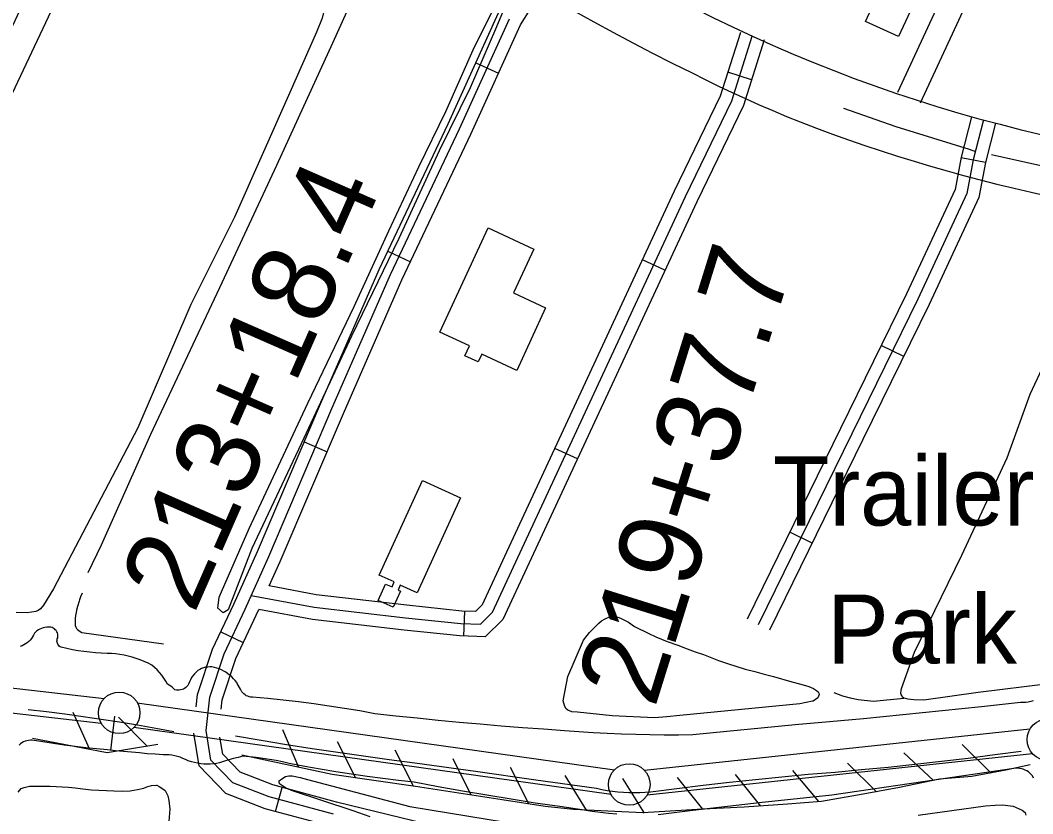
# Model space of a CAD drawing. Extents: x 3704301 to 3742427, y 506229 to 532009.
# Drawn here: x 3716465 to 3717682, y 522042 to 522996 of the extents above; entities that cross this region are included whole.
import ezdxf

# ---------------------------------------------------------------- set-up
doc = ezdxf.new("R2010")
doc.units = 0
for name, color, linetype in [('V-BLDG-IDEN', 7, 'Continuous'), ('V-BLDG-OTLN', 7, 'Continuous'), ('V-FLOD-BASE', 7, 'Continuous'), ('V-LEVE-TOET', 7, 'Continuous'), ('V-RAIL-TRAK', 7, 'Continuous'), ('V-ROAD-CNTR', 7, 'Continuous'), ('V-RRAP-FSHR', 7, 'Continuous'), ('V-SITE-OTLN', 7, 'Continuous'), ('V-SITE-VEGE', 7, 'Continuous'), ('V-SURV-IDEN', 7, 'Continuous'), ('V-SURV-LINE', 7, 'Continuous'), ('V-TOPO-SHOR', 7, 'Continuous'), ('V-UTIL-LINE', 7, 'Continuous')]:
    doc.layers.add(name, color=color, linetype=linetype)

msp = doc.modelspace()

# ---------------------------------------------------------------- linework, layer by layer
at = {"layer": 'V-BLDG-OTLN'}
for points in [[(3717592.6, 523131.4), (3717520.7, 522976.2), (3717481.1, 522994.5), (3717552.9, 523149.7)], [(3716969.2, 522620.9), (3717027.3, 522746.2), (3717082.2, 522720.7), (3717057.7, 522668), (3717096.4, 522650), (3717061.6, 522574.9), (3717019.5, 522594.4), (3717015.2, 522585.1), (3716999.3, 522592.5), (3717004.8, 522604.4)], [(3716994.1, 522421.6), (3716942, 522307.4), (3716921.7, 522316.7), (3716919, 522310.9), (3716921.8, 522309.6), (3716913, 522290.3), (3716895.1, 522298.5), (3716904, 522318.1), (3716911.7, 522314.6), (3716914.4, 522320.6), (3716896.3, 522328.9), (3716948.2, 522442.6)]]:
    msp.add_lwpolyline(points, close=True, dxfattribs=at)
at = {"layer": 'V-FLOD-BASE'}
for points in [[(3716649.4, 522140.4), (3716627.6, 522144.5), (3716605.9, 522148.4), (3716584, 522152.1), (3716562.2, 522155.5), (3716540.3, 522158.7), (3716518.4, 522161.7), (3716496.4, 522164.4), (3716474.4, 522166.9)], [(3717668.2, 522116.9), (3717636.3, 522112.7), (3717604.3, 522108.6), (3717572.4, 522104.8), (3717540.4, 522101.2), (3717508.4, 522097.8), (3717476.3, 522094.7), (3717444.3, 522091.7), (3717412.2, 522089), (3717380.5, 522086), (3717348.9, 522082.8), (3717317.3, 522079.4), (3717285.7, 522075.8), (3717254.1, 522071.9), (3717222.6, 522067.9), (3717216.1, 522067.4), (3717209.5, 522067.1), (3717203, 522067), (3717196.5, 522067.1), (3717189.9, 522067.4), (3717183.4, 522068), (3717176.9, 522068.7), (3717170.4, 522069.7), (3717164, 522070.9), (3717157.6, 522072.2), (3717084.8, 522082.5), (3717012, 522092.7), (3716939.2, 522102.7), (3716908.3, 522106.8), (3716877.5, 522111.1), (3716846.6, 522115.5), (3716815.8, 522120.2), (3716785, 522125), (3716754.3, 522129.9), (3716723.6, 522135.1)]]:
    msp.add_lwpolyline(points, dxfattribs=at)
at = {"layer": 'V-LEVE-TOET'}
for points in [[(3716511.6, 522243.6), (3716510.7, 522244.5), (3716510, 522245.7), (3716509.4, 522246.9), (3716509.1, 522248.2), (3716508.9, 522249.5), (3716509, 522250.8), (3716509.3, 522252.2), (3716509.8, 522253.4), (3716510, 522254.9), (3716510, 522256.4), (3716509.8, 522258), (3716509.4, 522259.4), (3716508.7, 522260.8), (3716507.9, 522262.1), (3716506.9, 522263.2), (3716505.8, 522264.2), (3716504.5, 522265.1), (3716503.1, 522265.7), (3716501.7, 522266.1), (3716500.2, 522266.4), (3716498.6, 522266.4), (3716496.5, 522266.3), (3716494.4, 522266), (3716492.4, 522265.5), (3716490.3, 522264.8), (3716488.4, 522264), (3716486.6, 522262.9), (3716484.8, 522261.7), (3716483.2, 522260.4), (3716481.7, 522258.9), (3716480.7, 522256.7), (3716479.6, 522254.6), (3716478.2, 522252.6), (3716476.7, 522250.7), (3716475, 522249), (3716473.1, 522247.5), (3716471.1, 522246.1), (3716469.1, 522244.9), (3716466.9, 522243.9), (3716464.6, 522243.1)], [(3716714.9, 522210), (3716714.5, 522210.4), (3716712, 522212.1), (3716709.4, 522213.6), (3716706.7, 522215), (3716703.9, 522216.1), (3716701, 522217.1), (3716698.1, 522217.9), (3716695.1, 522218.5), (3716692.6, 522218.6), (3716690.1, 522218.4), (3716687.6, 522218.1), (3716685.2, 522217.4), (3716682.8, 522216.6), (3716680.6, 522215.5), (3716678.4, 522214.3), (3716676.3, 522212.3), (3716674.3, 522210.3), (3716672.4, 522208), (3716670.8, 522205.6), (3716669.4, 522203.1), (3716668.2, 522200.4), (3716667.2, 522197.7), (3716666.3, 522196.3), (3716665.1, 522194.9), (3716663.9, 522193.7), (3716662.4, 522192.7), (3716660.9, 522191.9), (3716659.3, 522191.2), (3716657.6, 522190.8), (3716655.9, 522190.5), (3716654.1, 522190.5), (3716652.4, 522190.7), (3716650.7, 522191), (3716649.1, 522192.6), (3716647.4, 522194.1), (3716645.7, 522195.4), (3716643.8, 522196.7), (3716641.9, 522197.7), (3716639.8, 522201.4), (3716637.4, 522205), (3716634.9, 522208.5), (3716632.2, 522211.8), (3716629.3, 522214.9), (3716626.3, 522218), (3716623.1, 522220.8), (3716618.5, 522223.1), (3716613.9, 522225.2), (3716609.1, 522227.1), (3716604.3, 522228.8), (3716599.4, 522230.2), (3716594.5, 522231.5), (3716589.5, 522232.6), (3716584.5, 522233.5), (3716579.4, 522234.1), (3716574.3, 522234.5), (3716569.2, 522234.8), (3716562.2, 522235), (3716555.2, 522235.4), (3716548.3, 522236.1), (3716541.3, 522236.9), (3716534.4, 522237.9), (3716527.5, 522239.1), (3716520.7, 522240.5), (3716513.9, 522242.1), (3716512.7, 522242.8), (3716511.6, 522243.6)], [(3716891.2, 522162.3), (3716872.9, 522165.6), (3716854.5, 522168.7), (3716836.1, 522171.5), (3716817.7, 522174.1), (3716799.3, 522176.5), (3716780.8, 522178.7), (3716762.3, 522180.6), (3716743.8, 522182.3), (3716741.6, 522182.3), (3716739.9, 522182.6), (3716738.2, 522183.2), (3716736.5, 522183.9), (3716735, 522184.9), (3716733.6, 522186), (3716732.3, 522187.3), (3716731.1, 522188.7), (3716730.2, 522190.2), (3716729.4, 522191.9), (3716725.5, 522198.7), (3716725.1, 522199.6), (3716723.3, 522202), (3716721.3, 522204.3), (3716719.2, 522206.5), (3716716.9, 522208.5), (3716714.9, 522210)], [(3717682.6, 522177.8), (3717679.6, 522177), (3717676.6, 522176.3), (3717673.6, 522175.8), (3717670.5, 522175.6), (3717667.5, 522175.6), (3717620.3, 522170.5), (3717573.1, 522165.6), (3717525.9, 522160.8), (3717478.7, 522156.1), (3717437.6, 522152.5), (3717396.5, 522148.7), (3717355.4, 522144.9), (3717314.3, 522140.9), (3717273.2, 522136.7), (3717256.1, 522136.6), (3717238.9, 522136.6), (3717221.8, 522136.8), (3717204.7, 522137.1), (3717187.6, 522137.7), (3717170.5, 522138.4), (3717153.4, 522139.4), (3717136.3, 522140.5), (3717119.2, 522141.8), (3717093.9, 522143.6), (3717068.5, 522145.4), (3717043.1, 522147.4), (3717017.8, 522149.6), (3716992.4, 522151.8), (3716967.1, 522154.2), (3716941.8, 522156.8), (3716916.4, 522159.5), (3716891.2, 522162.3)], [(3716588.8, 522116.8), (3716579.2, 522117.8), (3716569.6, 522118.8), (3716556.6, 522120), (3716543.7, 522121.4), (3716530.7, 522122.9), (3716517.7, 522124.5), (3716504.8, 522126.3), (3716491.9, 522128.3), (3716479, 522130.3), (3716476.9, 522130.4), (3716474.7, 522130.2), (3716472.6, 522129.8), (3716470.6, 522129.1), (3716468.6, 522128.3), (3716466.7, 522127.3), (3716465, 522126), (3716463.3, 522124.6)], [(3716710.4, 522105.1), (3716704.4, 522103.1), (3716700.7, 522102.4), (3716696.9, 522101.9), (3716693.1, 522101.6), (3716689.3, 522101.6), (3716685.5, 522101.7), (3716681.7, 522102.1), (3716677.9, 522102.7), (3716674.1, 522103.5), (3716670.5, 522104.5), (3716666.8, 522105.7), (3716663.3, 522107.1), (3716660.2, 522108.6), (3716657, 522109.9), (3716653.8, 522110.9), (3716650.4, 522111.7), (3716647, 522112.3), (3716643.6, 522112.7), (3716640.1, 522112.9), (3716636.6, 522112.8), (3716627.1, 522113.5), (3716617.5, 522114.2), (3716608, 522115.1), (3716598.4, 522115.9), (3716588.8, 522116.8)], [(3717182, 522041.6), (3717172.1, 522042.5), (3717162.2, 522043.6), (3717152.4, 522044.9), (3717142.6, 522046.5), (3717113.3, 522050.6), (3717084, 522054.9), (3717054.8, 522059.4), (3717025.6, 522064.2), (3716996.4, 522069.2), (3716967.3, 522074.5), (3716938.3, 522080), (3716919.4, 522082.1), (3716900.6, 522084.4), (3716881.7, 522086.9), (3716863, 522089.6), (3716844.2, 522092.5), (3716825.5, 522095.6), (3716806.8, 522099), (3716788.1, 522102.5), (3716780.2, 522104.3), (3716772.3, 522105.9), (3716764.3, 522107.3), (3716756.3, 522108.6), (3716748.3, 522109.6), (3716740.2, 522110.5), (3716732.2, 522111.3), (3716726.6, 522109.8), (3716721, 522108.3), (3716715.5, 522106.7), (3716710.4, 522105.1)], [(3717683.1, 522084.9), (3717681.8, 522087.4), (3717680.3, 522089.2), (3717678.6, 522090.8), (3717676.8, 522092.3), (3717674.9, 522093.5), (3717672.8, 522094.6), (3717670.7, 522095.5), (3717668.4, 522096.1), (3717666.2, 522096.5), (3717663.8, 522096.7), (3717661.5, 522096.7), (3717659.2, 522096.4), (3717440.5, 522064.2), (3717398.7, 522059.9), (3717356.9, 522055.4), (3717315.1, 522050.8), (3717273.4, 522045.9), (3717231.6, 522040.9)]]:
    msp.add_lwpolyline(points, dxfattribs=at)
at = {"layer": 'V-RAIL-TRAK'}
for points in [[(3717089, 523032.2), (3717094.4, 523028.9), (3717112.8, 523017.7), (3717131.3, 523006.8), (3717154.5, 522993.8), (3717177.8, 522981.1), (3717201.2, 522968.6), (3717224.8, 522956.4), (3717248.5, 522944.4), (3717272.4, 522932.7), (3717288.3, 522924.6), (3717304.4, 522916.7), (3717320.5, 522909), (3717328.6, 522905.3)], [(3717328.6, 522905.3), (3717336.7, 522901.6), (3717353.1, 522894.3), (3717369.5, 522887.2), (3717386, 522880.3), (3717402.6, 522873.7), (3717421.9, 522866.3), (3717441.3, 522859.1), (3717460.7, 522852.2), (3717480.3, 522845.4), (3717499.9, 522838.9), (3717519.6, 522832.5), (3717539.3, 522826.4), (3717559.1, 522820.5), (3717579, 522814.8), (3717598.9, 522809.3), (3717618.9, 522804), (3717639, 522798.9), (3717659.6, 522793.8), (3717680.3, 522789), (3717701.1, 522784.4)]]:
    msp.add_lwpolyline(points, dxfattribs=at)
at = {"layer": 'V-ROAD-CNTR'}
for p, q in [((3717012.3, 522944.7), (3717039.7, 522932.3)), ((3717344.1, 522924.4), (3717315.5, 522933.4)), ((3717625.2, 522824.8), (3717595.8, 522830.3)), ((3716906.7, 522718.4), (3716933.9, 522705.6)), ((3717239.9, 522695.3), (3717212.7, 522707.9)), ((3717526.9, 522591.7), (3717500, 522605)), ((3716806, 522489), (3716833.6, 522477.2)), ((3717134.6, 522468.6), (3717107.4, 522481.2)), ((3717416.8, 522367.3), (3717389.8, 522380.5)), ((3716998, 522255.5), (3716999.2, 522285.5)), ((3716705.7, 522260.5), (3716732.9, 522247.9)), ((3716771.7, 522044.7), (3716779.5, 522073.6))]:
    msp.add_line(p, q, dxfattribs=at)
for points in [[(3717519.8, 522909.2), (3717847.3, 523615.3), (3717883.3, 523693.9)], [(3717547, 522896.5), (3717874.6, 523602.8), (3717910.7, 523681.6)], [(3716676.3, 522170.4), (3716678, 522185.3), (3716696, 522239.8), (3716721.4, 522294.1), (3716749.8, 522357.2), (3716825.6, 522534.9), (3716896.3, 522696.3), (3716979.1, 522871.5), (3717039.6, 523004.8), (3717084.1, 523075.5), (3717102.4, 523110.2)], [(3716764.1, 522315.8), (3716777.3, 522345.2), (3716853.2, 522523), (3716923.6, 522683.9), (3717006.3, 522858.9), (3717066, 522990.5), (3717110.1, 523060.5), (3717128.9, 523096.2)], [(3716841.3, 522041.4), (3716763.9, 522062.3), (3716720.4, 522079.1), (3716694, 522106.6), (3716688.2, 522142.2), (3716692.7, 522182), (3716710, 522234.3), (3716735, 522287.8), (3716763.6, 522351.2), (3716839.4, 522529), (3716910, 522690.1), (3716992.7, 522865.2), (3717052.8, 522997.6)], [(3716742.5, 522304.5), (3716818.2, 522290.5), (3716927.8, 522277.6), (3716994.5, 522270.7), (3717017.9, 522269.8), (3717032.5, 522284.3), (3717062.9, 522350.1), (3717149.6, 522536.4), (3717264.5, 522783.9), (3717320.3, 522899), (3717344.9, 522976.6)], [(3717359.2, 522972.1), (3717334.3, 522893.5), (3717278.1, 522777.5), (3717163.2, 522530.1), (3717076.5, 522343.8), (3717045, 522275.6), (3717023.9, 522254.6), (3716993.4, 522255.7), (3716926.2, 522262.7), (3716816, 522275.6), (3716751.4, 522287.6)], [(3717330.6, 522981.1), (3717306.3, 522904.6), (3717251, 522790.4), (3717136, 522542.7), (3717049.3, 522356.4), (3717020, 522293.1), (3717011.9, 522285), (3716995.5, 522285.6), (3716929.5, 522292.6), (3716820.5, 522305.3), (3716764.1, 522315.8)], [(3717608.3, 522879.7), (3717595.9, 522831.2), (3717588.6, 522792.2), (3717530.4, 522667), (3717451, 522505.1), (3717338.5, 522275.9)], [(3717622.8, 522876), (3717610.6, 522827.9), (3717603, 522787.5), (3717544, 522660.6), (3717464.5, 522498.5), (3717352, 522269.3)], [(3717637.4, 522872.3), (3717625.2, 522824.7), (3717617.4, 522782.9), (3717557.5, 522654.1), (3717477.9, 522491.9), (3717365.4, 522262.7)], [(3716706.2, 522167.8), (3716707.5, 522178.8), (3716723.9, 522228.7), (3716751.4, 522287.6)], [(3717037.6, 521978.2), (3716992.4, 521989), (3716837.5, 522026.9), (3716759.2, 522048.1), (3716711.9, 522066.3), (3716680, 522099.6), (3716673.6, 522138.8)], [(3717294.9, 521937.6), (3717281.9, 521940.2), (3717184.3, 521971.9), (3717095.7, 521995.1), (3716999.5, 522018.2), (3716845, 522055.9), (3716768.6, 522076.6), (3716729, 522091.9), (3716708.1, 522113.6), (3716704.8, 522133.9)]]:
    msp.add_lwpolyline(points, dxfattribs=at)
msp.add_arc((3718103.2, 524637.5), 1825.8, 243.0053, 269.4245, dxfattribs=at)
at = {"layer": 'V-RRAP-FSHR'}
for p, q in [((3716548.3, 522119.2), (3716528.4, 522163.8)), ((3716617.2, 522123.2), (3716582.9, 522158)), ((3716799.5, 522097.8), (3716780.6, 522142.8)), ((3716868.3, 522084.9), (3716846.2, 522128.5)), ((3716937.6, 522075), (3716915.5, 522118.6)), ((3717632, 522091), (3717597.1, 522125.2)), ((3717006.8, 522064.3), (3716985.2, 522108.1)), ((3717562.6, 522082), (3717527, 522115.3)), ((3717076, 522053.8), (3717054.1, 522097.5)), ((3717425, 522056.6), (3717393.6, 522094.1)), ((3717494, 522068.4), (3717459.4, 522103)), ((3717145.5, 522046.4), (3717119.7, 522087.8)), ((3717215.4, 522042.9), (3717189.4, 522084.2)), ((3717285.3, 522047.6), (3717254.8, 522085.7)), ((3717355.2, 522051.2), (3717324.6, 522089.3))]:
    msp.add_line(p, q, dxfattribs=at)
for points in [[(3716630.1, 522125.4), (3716569.2, 522115.1), (3716479.6, 522132.6)], [(3717678.8, 522100.7), (3717649.5, 522094.3), (3717608.7, 522086.6), (3717570.1, 522083.5), (3717522, 522073.4), (3717478, 522065.6), (3717427.9, 522056.9), (3717387.2, 522053.4), (3717335, 522049.9), (3717285.4, 522047.6), (3717246.1, 522045), (3717213.3, 522043), (3717179.7, 522044.6), (3717129.8, 522047.2), (3717096, 522050.9), (3717044, 522058.6), (3716939.8, 522074.7), (3716839.9, 522089), (3716731.1, 522112.6)]]:
    msp.add_lwpolyline(points, dxfattribs=at)
at = {"layer": 'V-SITE-OTLN'}
msp.add_lwpolyline([(3716156.7, 522353.4), (3716516.2, 523119.1), (3716532.5, 523165.4), (3716549.1, 523192.8), (3716555.7, 523203.2), (3716586.7, 523185), (3716580, 523166.6), (3716824.5, 523017.3), (3716827, 523014.8), (3716829.8, 523008.3), (3716829.4, 523005.1), (3716827.8, 522998.5), (3716821, 522981.4), (3716788.9, 522908.9), (3716722.5, 522759.3), (3716669.7, 522654.2), (3716606.2, 522505.9), (3716504.6, 522312.2), (3716492.7, 522292.7), (3716488.9, 522288.3), (3716486.4, 522286.5), (3716483.4, 522285.3), (3716473, 522283.5), (3716459.8, 522283.8)], dxfattribs=at)
at = {"layer": 'V-SITE-VEGE'}
msp.add_lwpolyline([(3717402, 522174.3), (3717257.8, 522160.2), (3717242.2, 522158.5), (3717227.3, 522157.4), (3717176.4, 522159.7), (3717134.7, 522164.1), (3717127.9, 522164.7), (3717123.1, 522166.5), (3717121.1, 522168.2), (3717119.4, 522170.8), (3717117.3, 522177.7), (3717123.2, 522207), (3717141.9, 522250.8), (3717149.2, 522259.8), (3717155, 522266), (3717160.4, 522271.2), (3717163.7, 522274), (3717168.1, 522276.5), (3717173.1, 522278.6), (3717175.8, 522279.2), (3717183.3, 522278.5), (3717186.4, 522277.2), (3717196, 522272.3), (3717203.3, 522267.2), (3717220.5, 522258.6), (3717228.7, 522254.8), (3717242.4, 522249.2), (3717255.5, 522244.5), (3717266.7, 522240.2), (3717276.1, 522236.8), (3717286, 522233.4), (3717296.3, 522229.6), (3717304.4, 522226.4), (3717315, 522222.7), (3717336.2, 522215.9), (3717348.1, 522213), (3717359.2, 522209.9), (3717370.2, 522207), (3717392.2, 522200.7), (3717403.4, 522197.8), (3717412.8, 522195), (3717418.4, 522192.5), (3717422.1, 522190.3), (3717424.1, 522188.4), (3717424.9, 522187.1), (3717425.4, 522185.5), (3717423.8, 522181.3), (3717418.1, 522177.5), (3717417.3, 522177.2)], close=True, dxfattribs=at)
for points in [[(3716885.6, 522038.5), (3716865.1, 522045.4), (3716790.7, 522070), (3716783.6, 522073), (3716776.4, 522077.9), (3716776.1, 522080.9), (3716776.1, 522081.7), (3716780.5, 522084.8), (3716783.6, 522086.7), (3716787.6, 522087.5), (3716791.5, 522087.5), (3716801.1, 522085.7), (3716810, 522083.2), (3716933.3, 522050.9), (3717072.4, 522027.7)], [(3716462.4, 522067.9), (3716465.9, 522072.3), (3716469.5, 522073.6), (3716476, 522075), (3716481.9, 522075.3), (3716488.2, 522075.2), (3716488.6, 522075.2), (3716500.2, 522075.1), (3716522.6, 522073.8), (3716530.8, 522073), (3716540, 522071.8), (3716550.5, 522070.7), (3716577.1, 522069.6), (3716588.1, 522069.2), (3716597, 522069.6), (3716605.6, 522071), (3716613.2, 522072.9), (3716617, 522074.3), (3716622.6, 522075.9), (3716628.5, 522076.4), (3716629, 522076.4), (3716631.6, 522074.9), (3716636.2, 522072), (3716638.8, 522069.9), (3716642.1, 522063.6), (3716643.5, 522058.1), (3716644.4, 522047.7), (3716643.3, 522033.1)], [(3717544.2, 522040.2), (3717625.2, 522051.4), (3717636.7, 522052.3), (3717645.6, 522052.6), (3717658.5, 522051.1), (3717669.5, 522046.5), (3717672.8, 522043.7), (3717673.8, 522040.4)]]:
    msp.add_lwpolyline(points, dxfattribs=at)
at = {"layer": 'V-SURV-LINE'}
for points in [[(3715603.4, 522290.9), (3716565.5, 522180.5)], [(3716562.1, 522150.7), (3715599.9, 522261.1)], [(3716605.5, 522175.4), (3717179.2, 522094.9)], [(3717175, 522065.1), (3716601.4, 522145.7)], [(3717215.2, 522094.3), (3717678.7, 522143.9)], [(3717681.9, 522114.1), (3717218.4, 522064.4)]]:
    msp.add_lwpolyline(points, dxfattribs=at)
for centre in [(3716583.7, 522163.3), (3717700.2, 522131.1), (3717196.9, 522077.2)]:
    msp.add_circle(centre, 25, dxfattribs=at)
at = {"layer": 'V-TOPO-SHOR'}
for p, q in [((3717605.8, 522840.8), (3717613.3, 522838.1)), ((3717632.5, 522834.4), (3717759.2, 522806.2))]:
    msp.add_line(p, q, dxfattribs=at)
for points in [[(3716882.3, 523061.8), (3716840, 522968.2), (3716772.9, 522821.1), (3716704.2, 522674), (3716621.4, 522497.8), (3716561.9, 522365), (3716546.1, 522331.5)], [(3717054.8, 523033.5), (3717044.2, 523025.9), (3717040.4, 523021.5), (3717033, 523008.1), (3717010.3, 522963.3), (3716976.2, 522885.9), (3716943.4, 522819.3), (3716907.5, 522742.4), (3716865.8, 522651.2), (3716810, 522535.3), (3716739.7, 522384.6), (3716703.3, 522301.8), (3716701.7, 522289.6), (3716708.6, 522283.7)], [(3717054.8, 523033.5), (3717051, 523020.8), (3717036.2, 522985), (3717005.6, 522914.5), (3716968.5, 522838.9), (3716920, 522733.4), (3716862.9, 522616.2), (3716805.7, 522493.5), (3716743.3, 522360.9), (3716714.6, 522287.3), (3716708.6, 522283.7)], [(3717454.6, 522890.3), (3717517.5, 522868.1), (3717605.8, 522840.8)], [(3717700.8, 522198.2), (3717616.4, 522187.6), (3717551.1, 522178.7), (3717539, 522178.9), (3717531.7, 522179.9), (3717527.2, 522180.9), (3717525.4, 522182.3), (3717524.5, 522184), (3717523.9, 522185.4), (3717523.6, 522187.3), (3717523.9, 522189.7), (3717524.1, 522192.4), (3717539.8, 522236.2), (3717596.7, 522352.9), (3717651.1, 522469.9), (3717670.7, 522523.1), (3717679.1, 522546.2), (3717751, 522700.6), (3717771.6, 522744.3)], [(3716539.3, 522307.3), (3716537.3, 522302.8), (3716535.9, 522299), (3716535.4, 522297.4), (3716533.4, 522291.1), (3716532.3, 522286.9), (3716531.8, 522284), (3716531.1, 522280.5), (3716530.8, 522276.9), (3716530.7, 522273.7), (3716530.6, 522270.4), (3716530.9, 522268.4), (3716531.6, 522266.3), (3716532.5, 522264.7), (3716533.5, 522263.5), (3716535, 522262.3), (3716536.6, 522261), (3716538.7, 522260), (3716637.1, 522246.4)], [(3717442.8, 522187.6), (3717453.3, 522183.7), (3717462.7, 522181.3), (3717472.3, 522179.3), (3717490.6, 522177.3), (3717527.2, 522180.9)]]:
    msp.add_lwpolyline(points, dxfattribs=at)
at = {"layer": 'V-UTIL-LINE'}
msp.add_line((3716573.8, 522117.9), (3716578.4, 522159.3), dxfattribs=at)
msp.add_lwpolyline([(3716521.8, 523050.2), (3716451.5, 522900.3), (3716403.3, 522793.7), (3716415.4, 522787.7), (3716407, 522769.3), (3716414, 522766.2)], dxfattribs=at)

# ---------------------------------------------------------------- texts
at = {"layer": 'V-BLDG-IDEN'}
for s, p in [('Trailer', (3717369.7, 522388.5)), ('Park', (3717434.9, 522222.5))]:
    msp.add_text(s, height=83, dxfattribs=at).set_placement(p)
at = {"layer": 'V-SURV-IDEN'}
for s, rotation, p in [('213+18.4', 66.3119, (3716673.6, 522280.9)), ('219+37.7', 72.7051, (3717227.5, 522167.7))]:
    msp.add_text(s, height=100, rotation=rotation, dxfattribs=at).set_placement(p)

doc.saveas('drawing.dxf')
